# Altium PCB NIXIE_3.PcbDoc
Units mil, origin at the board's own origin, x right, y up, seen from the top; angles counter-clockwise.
Board outline 3937.01 x 1062.99 mil, 2 copper layers (Top Layer, Bottom Layer); 12 components, 35 nets, 109 pads, 0 vias.
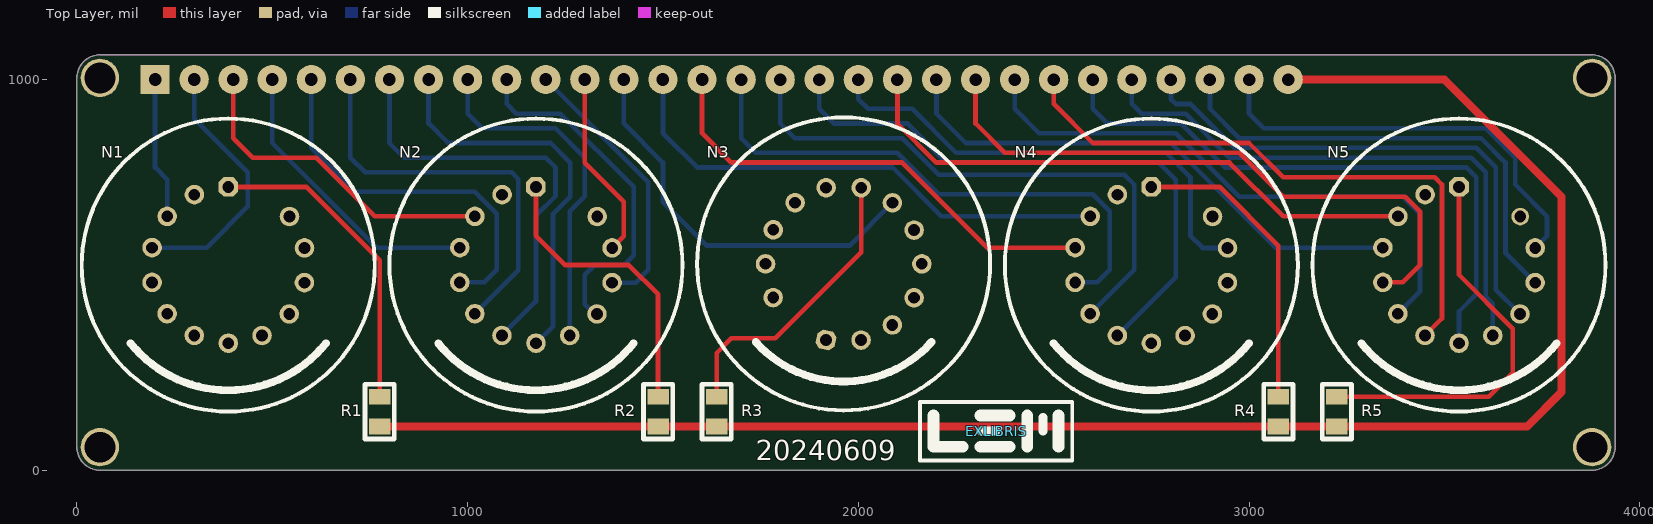
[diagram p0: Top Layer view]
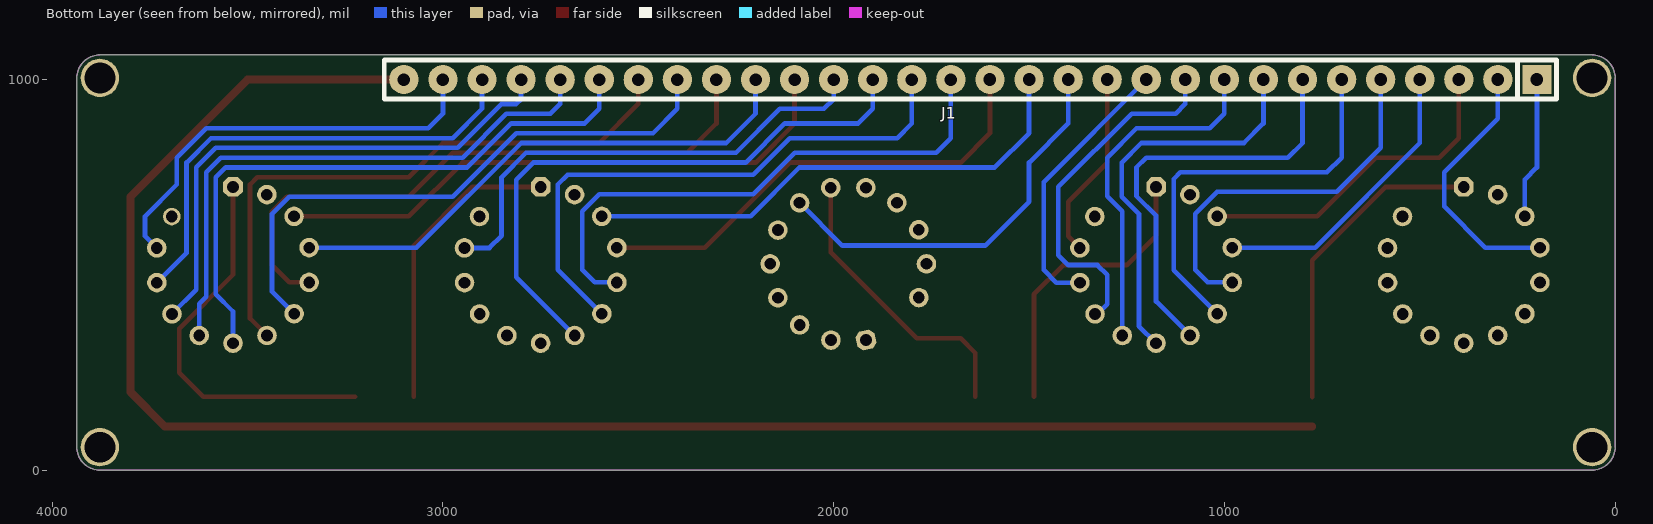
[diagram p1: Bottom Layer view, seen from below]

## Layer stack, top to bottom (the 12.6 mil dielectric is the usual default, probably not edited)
Top Solder: solder mask 0.4, Solder Resist, Dk 3.5
Top Layer: signal copper 1.4
Dielectric 1: dielectric 12.6, FR-4, Dk 4.8
Bottom Layer: signal copper 1.4
Bottom Solder: solder mask 0.4, Solder Resist, Dk 3.5

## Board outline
0,59.06 0,1003.94 cw(c59.06,1003.94) 59.06,1062.99 3877.95,1062.99 cw(c3877.95,1003.94) 3937.01,1003.94 3937.01,59.06 cw(c3877.95,59.06) 3877.95,0 59.06,0 cw(c59.06,59.06)

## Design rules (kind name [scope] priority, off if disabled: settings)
Clearance [All] p1: gap=3.94 ignorepadtopadclearanceinfootprint=TRUE
ComponentClearance [All] p1: gap=0 collisioncheckmode=3 verticalgap=100000 showdistances=TRUE
Height [All] p1: minheight=0 maxheight=5000 prefheight=500
PolygonConnect [All] p1: connectstyle=Relief reliefconductorwidth=10 reliefentries=4 polygonreliefangle="90 Angle" airgapwidth=10
RoutingCorners [All] p1: cornerstyle=45-Degree minsetback=25 maxsetback=25
RoutingVias [All] p1: holewidth=28 width=50 viastyle="Through Hole" minholewidth=28 minwidth=50 maxholewidth=28 maxwidth=50
SolderMaskExpansion [All] p1: expansion=4
Width [All] p1: maxlimit=50 minlimit=10 preferedwidth=15
27 further rules are at their usual default settings.

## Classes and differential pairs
component class NIXIE_3: J1 N1 N2 N3 N4 N5 R1 R2 R3 R4 R5

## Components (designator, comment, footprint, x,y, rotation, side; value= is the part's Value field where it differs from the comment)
EXLIBRIS "EXLIBRIS" EXLBS_2 2352.5,100 r0 top
J1 "30pin" SIL30 1650.11,999.99 r0 bottom locked
N1 "LC531" "NIXIE LC531"#1 387.5,525 r0 top locked
N2 "LC531" "NIXIE LC531"#1 1175,525 r0 top locked
N3 "LL561" "NIXIE LL561" 1962.5,528.12 r0 top locked
N4 "LC531" "NIXIE LC531"#1 2750,525 r0 top locked
N5 "LC531" "NIXIE LC531"#2 3537.5,525 r0 top locked
R1 "20K" SMD_R_0805 775,150 r270 top
R2 "20K" SMD_R_0805 1487.5,150 r270 top
R3 "62K" SMD_R_0805 1637.5,150 r270 top
R4 "20K" SMD_R_0805 3075,150 r270 top
R5 "20K" SMD_R_0805 3225,150 r270 top

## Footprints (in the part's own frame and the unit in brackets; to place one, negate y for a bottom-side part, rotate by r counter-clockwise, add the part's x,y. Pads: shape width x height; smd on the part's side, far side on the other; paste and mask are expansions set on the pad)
EXLBS_2 [mil] "Exlibris TOP Layer Hight = 180mil"
  silkscreen extent -195,-75 195,75
"NIXIE LC531"#1 [mil] "Lampa Nixie LC531 NUMERYCZNA"
  oct 50x50 hole 30: 1(-0.04,200)
  round 50 hole 30: 2(-86.77,180.22) 3(-156.34,124.78) 4(-194.99,44.65) 5(-195.07,-44.31) 6(-156.56,-124.5) 7(-87.08,-180.06) 8(-0.04,-200) 9(86.38,-180.37) 10(156.05,-125.05) 11(194.84,-44.99) 12(195.07,43.97) 13(156.7,124.23)
  silkscreen extent -375,-375 375,375
"NIXIE LC531"#2 [mil] "Lampa Nixie LC531 NUMERYCZNA"
  oct 50x50 hole 30: 1(-0.04,200)
  round 50 hole 30: 2(-86.77,180.22) 3(-156.34,124.78) 4(-194.99,44.65) 5(-195.07,-44.31) 6(-156.56,-124.5) 7(-87.08,-180.06) 8(-0.04,-200) 9(86.38,-180.37) 10(156.05,-125.05) 11(194.84,-44.99) 12(195.07,43.97)
  round 45 hole 30: 13(156.7,124.23)
  silkscreen extent -375,-375 375,375
"NIXIE LL561" [mil] "Lampa Nixie LL561 ZNAKOWA"
  oct 50x50 hole 30 rot 168.75: 1(-45.16,-194.83)
  round 50 hole 30: 2(44.48,-194.99) 3(124.64,-156.41) 4(180.14,-86.89) 5(200,0) 6(180.29,86.57) 7(124.91,156.19) 8(44.82,194.91) 9(-45,195) 10(-124.37,156.63) 11(-179.99,87.2) 12(-200,0) 13(-180.44,-86.26)
  silkscreen extent -375,-375 375,375
SIL30 [mil] "Obudowa serial 30 pin"
  rect 75x75 hole 32: 1(-1450.11,-0.01)
  round 75 hole 32: 2(-1350.11,-0.01) 3(-1250.11,-0.01) 4(-1150.11,-0.01) 5(-1050.11,-0.01) 6(-950.11,-0.01) 7(-850.11,-0.01) 8(-750.11,-0.01) 9(-650.11,-0.01) 10(-550.11,-0.01) 11(-450.11,-0.01) 12(-350.11,-0.01) 13(-250.11,-0.01) 14(-150.11,-0.01) 15(-50.11,-0.01) 16(50,0) 17(150,0) 18(250,0) 19(350,0) 20(450,0) 21(550,0) 22(650,0) 23(750,0) 24(850,0) 25(950,0) 26(1050,0) 27(1150,0) 28(1250,0) 29(1350,0) 30(1450,0)
  silkscreen extent -1500,-50 1500,50, body extent -1500,-50 1500,50, height 309
SMD_R_0805 [mil] "Rozmiar 0805 -> 80x50mil"
  rect 40x55 smd: 1(-38,0) 2(38,0)
  silkscreen extent -70,-38 70,38, body extent -39,-24 39,25, height 31

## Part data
EXLIBRIS: library part EXLBR
J1: library part "CON 30pin"
N1 N2 N4 N5: library part "NIXIE LC531", "Lampa Numeryczna Nixie"
N3: library part "NIXIE LL561", "SIGN NEON LAMP"
R1 R2 R3 R4 R5: library part R, "Resistor"

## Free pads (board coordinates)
  round 98.43 hole 78.74: 0(59.06,1003.94) 0(59.06,59.06) 0(3877.95,59.06) 0(3877.95,1003.94)

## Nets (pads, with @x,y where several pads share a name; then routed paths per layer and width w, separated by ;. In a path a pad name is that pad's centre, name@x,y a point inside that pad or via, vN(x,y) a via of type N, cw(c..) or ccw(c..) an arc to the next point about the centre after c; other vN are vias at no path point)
NetJ1_1: J1.1 N1.3 | length 363.1
  Bottom Layer w12: J1.1 200,775 231.16,743.84 N1.3
NetJ1_2: J1.2 N1.4 | length 678.7
  Bottom Layer w12: N1.4@184.39,569.65 N1.4 332.15,569.65 437.5,675 437.5,762.5 300,900 J1.2
NetJ1_3: J1.3 N2.3 | length 851.6
  Top Layer w12: J1.3 400,850 450,800 612.5,800 762.5,650 1018.43,650 N2.3
NetJ1_4: J1.4 N2.4 | length 753.5
  Bottom Layer w12: J1.4 500,837.5 767.85,569.65 N2.4
NetJ1_5: J1.5 N2.5 | length 971.9
  Bottom Layer w12: J1.5 600,825 712.5,712.5 1018.75,712.5 1075,656.25 1075,512.5 1043.19,480.69 N2.5
NetJ1_6: J1.6 N2.6 | length 1043.2
  Bottom Layer w12: J1.6 700,800 737.5,762.5 1112.5,762.5 1129.69,745.31 1129.69,511.75 N2.6
NetJ1_7: J1.7 N2.7 | length 1100.2
  Bottom Layer w12: J1.7 800,837.5 837.5,800 1200,800 1225,775 1225,701.75 1175,651.75 1175,432.02 N2.7
NetJ1_8: J1.8 N2.8 | length 1015.2
  Bottom Layer w12: J1.8 900,887.5 950,837.5 1212.5,837.5 1262.5,787.5 1262.5,700 1218.75,656.25 1218.75,368.79 N2.8
NetJ1_9: J1.9 N2.9 | length 905.5
  Bottom Layer w12: J1.9 1000,912.5 1037.5,875 1225,875 1300,800 1300,701.12 1261.38,662.5 N2.9
NetJ1_10: J1.10 N2.10 | length 875.2
  Bottom Layer w12: 1100,962.5 1100,937.5 1125,912.5 1237.5,912.5 1425,725 1425,550 1400,525 1325,525 1300,500 1300,425 1325.05,399.95 N2.10
NetJ1_11: J1.11 N2.11 | length 702.4
  Bottom Layer w12: J1.11 1462.5,737.5 1462.5,512.5 1430.01,480.01 N2.11
NetJ1_12: J1.12 N2.12 | length 484.9
  Top Layer w12: J1.12 1300,787.5 1400,687.5 1400,598.9 N2.12
NetJ1_13: J1.13 N3.7 | length 1033.3
  Bottom Layer w12: J1.13 1400,887.5 1500,787.5 1500,687.5 1612.5,575 1978.09,575 N3.7 N3.7@2087.5,684.41
NetJ1_14: J1.14 N4.3 | length 1331.8
  Bottom Layer w12: J1.14@1500,1012.5 J1.14 1500,862.5 1587.5,775 2087.5,775 2212.72,649.78 N4.3
NetJ1_15: J1.15 N4.4 | length 1213.8
  Top Layer w12: J1.15 1600,862.5 1675,787.5 2112.5,787.5 2330.35,569.65 N4.4
NetJ1_16: J1.16 N4.5 | length 1423.4
  Bottom Layer w12: J1.16 1700.11,849.89 1737.5,812.5 2100,812.5 2206.25,706.25 2600,706.25 2643.75,662.5 2643.75,512.5 2611.94,480.69 N4.5
NetJ1_17: J1.17 N4.6 | length 1460.9
  Bottom Layer w12: J1.17 1800.11,887.39 1837.5,850 2112.5,850 2206.25,756.25 2681.25,756.25 2706.25,731.25 2706.25,513.31 N4.6
NetJ1_18: J1.18 N4.7 | length 1523.7
  Bottom Layer w12: J1.18 1900.11,924.89 1937.5,887.5 2125,887.5 2225,787.5 2768.75,787.5 2812.5,743.75 2812.5,493.75 2663.69,344.94 N4.7
NetJ1_19: J1.19 N4.12 | length 1240.7
  Bottom Layer w12: J1.19 2000.11,949.89 2025,925 2137.5,925 2250,812.5 2787.5,812.5 2850,750 2850,600 2881.03,568.97 N4.12
NetJ1_20: J1.20 N5.3 | length 1492.1
  Top Layer w12: J1.20 2100.11,887.39 2200,787.5 2950,787.5 3087.72,649.78 N5.3@3375.22,649.78
  Bottom Layer w12: N5.3@3375.22,649.78 N5.3
NetJ1_21: J1.21 N5.4 | length 1372
  Bottom Layer w12: J1.21 2200.11,912.39 2275,837.5 2800,837.5 3067.85,569.65 N5.4
NetJ1_22: J1.22 N5.5 | length 1594.2
  Top Layer w12: J1.22 2300,999.89 2300,887.5 2375,812.5 2975,812.5 3087.5,700 3400,700 3437.5,662.5 3437.5,525 3393.19,480.69 N5.5
NetJ1_23: J1.23 N5.6 | length 1502.9
  Bottom Layer w12: J1.23 2400.11,924.89 2462.5,862.5 2812.5,862.5 2975,700 3393.75,700 3437.5,656.25 3437.5,457.06 N5.6
NetJ1_24: J1.24 N5.7 | length 1545.9
  Top Layer w12: J1.24 2500.11,937.39 2600,837.5 3000,837.5 3087.5,750 3475,750 3493.75,731.25 3493.75,388.27 N5.7
NetJ1_25: J1.25 N5.8 | length 1571.8
  Bottom Layer w12: J1.25 2600.11,924.89 2637.5,887.5 2825,887.5 2937.5,775 3556.25,775 3581.25,750 3581.25,450 3537.46,406.21 N5.8
NetJ1_26: J1.26 N5.9 | length 1466.4
  Bottom Layer w12: J1.26 2700.11,937.39 2725,912.5 2837.5,912.5 2950,800 3568.75,800 3606.25,762.5 3606.25,443.75 3623.88,426.12 N5.9
NetJ1_27: J1.27 N5.10 | length 1354.5
  Bottom Layer w12: J1.27 2800.11,949.89 2812.5,937.5 2850,937.5 2962.5,825 3581.25,825 3631.25,775 3631.25,462.25 N5.10
NetJ1_28: J1.28 N5.11 | length 1227.2
  Bottom Layer w12: J1.28 2900.11,924.89 2975,850 3593.75,850 3656.25,787.5 3656.25,556.1 N5.11
NetJ1_29: J1.29 N5.12 | length 1092.4
  Bottom Layer w12: J1.29 3000.11,912.39 3037.5,875 3606.25,875 3681.25,800 3681.25,731.25 3762.5,650 3762.5,598.9 N5.12
NetJ1_30: J1.30 R1.2 R2.2 R3.2 R4.2 R5.2 | length 4385.6
  Top Layer w20: R1.2 R2.2 R3.2 R4.2 R5.2 3712,112 3800,200 3800,700 3500.01,999.99 J1.30
NetN1_1: N1.1 R1.1 | length 815.2
  Top Layer w12: N1.1 587.5,725 775,537.5 R1.1 R1.1@775,187.5
NetN2_1: N2.1 R2.1 | length 761.6
  Top Layer w12: N2.1 1175,724.96 1175,600 1250,525 1412.5,525 1487.5,450 R2.1
NetN3_8: N3.8 R3.1 | length 754.1
  Top Layer w12: R3.1 1637.5,300 1675,337.5 1787.5,337.5 2007.32,557.32 N3.8
NetN4_1: N4.1 R4.1 | length 774.2
  Top Layer w12: N4.1 2925,725 3075,575 R4.1
NetN5_1: N5.1 R5.1 | length 1007.7
  Top Layer w12: R5.1 3613,188 3675,250 3675,362.5 3537.46,500.04 N5.1
pads on no net: N1.2 N1.5 N1.6 N1.7 N1.8 N1.9 N1.10 N1.11 N1.12 N1.13 N2.2 N2.13 N3.1 N3.2 N3.3 N3.4 N3.5 N3.6 N3.9 N3.10 N3.11 N3.12 N3.13 N4.2 N4.8 N4.9 N4.10 N4.11 N4.13 N5.2 N5.13

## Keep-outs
Keep-Out Layer:
  the board outline again, w1

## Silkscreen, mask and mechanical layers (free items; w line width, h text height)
Top Overlay:
  text "20240609" at 1737.5,25 h51.18

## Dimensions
3877.95,1003.94 to 3877.95,59.06 on Top Overlay
3877.95,1062.99 to 3877.95,0 on Top Overlay
59.06,1003.94 to 3877.95,1003.94 on Top Overlay
0,1003.94 to 3937.01,1003.94 on Top Overlay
